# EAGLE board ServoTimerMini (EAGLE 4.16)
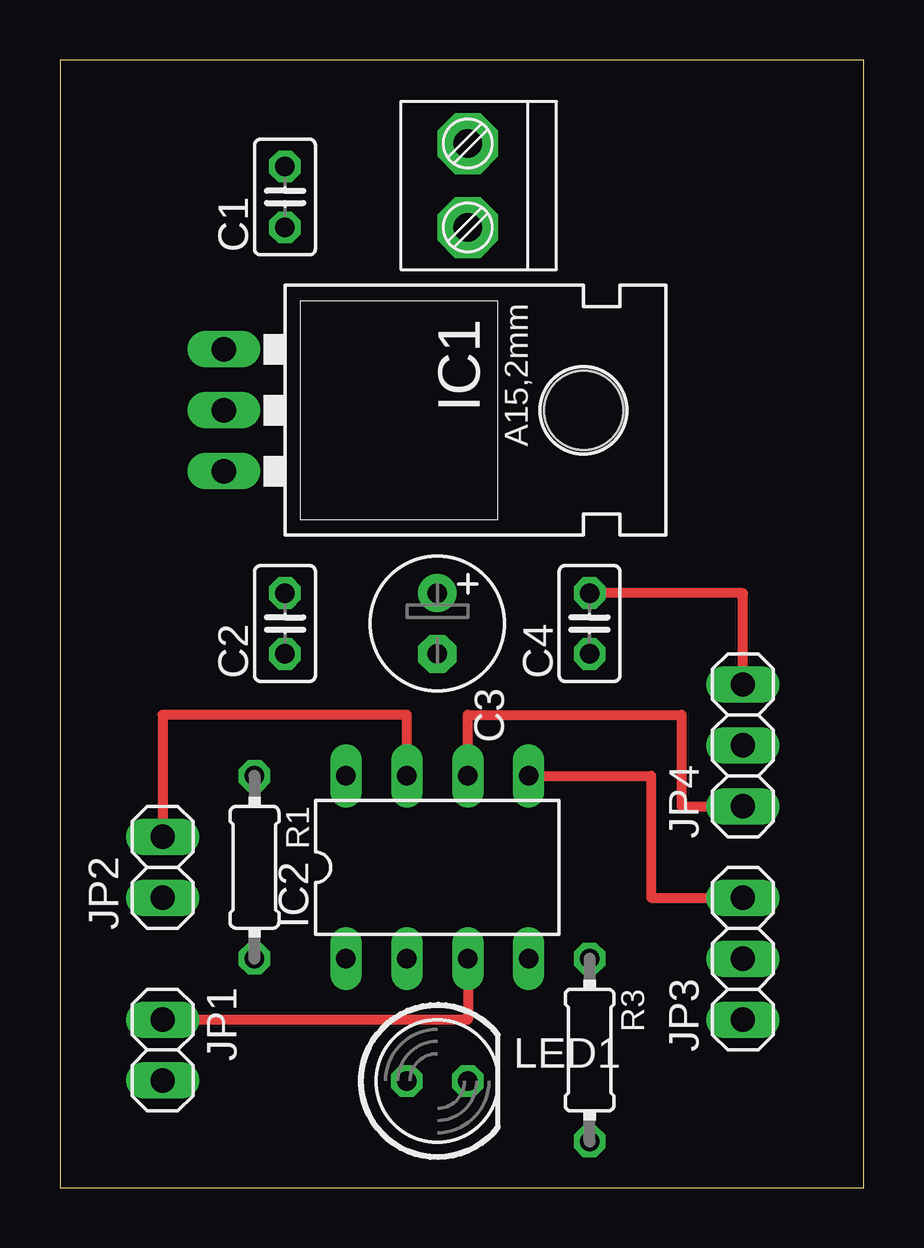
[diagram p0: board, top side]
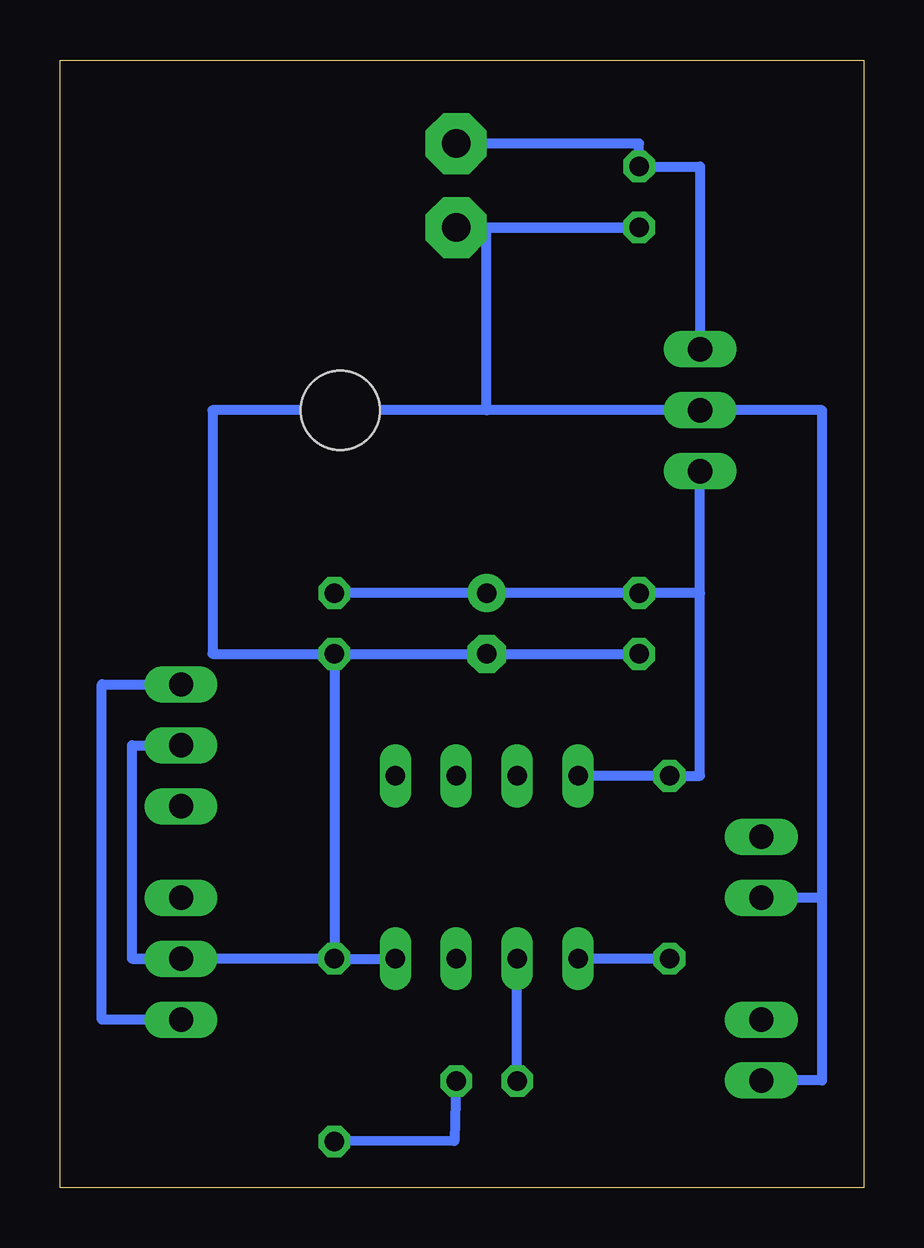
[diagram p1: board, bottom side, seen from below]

Size 33.52 x 47 mm. Coordinates in mm from the lower left corner, seen from the top.
Outline: 0,0 33.52,0 33.52,47 0,47 0,0
Copper layers (1*16): Top 0.035mm / dielectric 1.5mm / Bottom 0.035mm
Design rules "default": minimum track width 10mil, minimum drill 24mil, track to track 8mil, track to pad 8mil, pad to pad 8mil, via to via 8mil, smd to smd 8mil, copper to edge 40mil, drill to drill 8mil, minimum pad ring 10mil, minimum via ring 8mil, stop-mask expansion 4mil, vias tented up to drill 0mil, thermal gap 10mil
Net classes: 0 default: width 0.356 mm, drill 0.254 mm, clearance 0.61 mm; 1 GND: width 0.991 mm, drill 0.254 mm, clearance 0.61 mm; 2 VCC: width 0.356 mm, drill 0.254 mm, clearance 0.61 mm; 3 breit2: width 2.032 mm, drill 0.483 mm, clearance 0.61 mm; 4 breit3: width 2.54 mm, drill 0.61 mm, clearance 0.61 mm

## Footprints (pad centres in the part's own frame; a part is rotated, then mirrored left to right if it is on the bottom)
C025-025X050 = drill 0.813 octagon: 1 -1.27,0; 2 1.27,0
E2,5-6 = drill 0.813 pad 1.6 round: + -1.27,0 | drill 0.813 pad 1.6 octagon: - 1.27,0
78XXL = drill 1.016 long: GND 0,-3.81; IN -2.54,-3.81; OUT 2.54,-3.81 | hole 3.302: 0,11.176
DIL08 = drill 0.813 long: 1 -3.81,-3.81; 2 -1.27,-3.81; 3 1.27,-3.81; 4 3.81,-3.81; 5 3.81,3.81; 6 1.27,3.81; 7 -1.27,3.81; 8 -3.81,3.81
1X02 = drill 1.016 long: 1 -1.27,0; 2 1.27,0
1X03 = drill 1.016 long: 1 -2.54,0; 2 0,0; 3 2.54,0
LED5MM = drill 0.813 octagon: A -1.27,0; K 1.27,0
0204/7 = drill 0.813 octagon: 1 -3.81,0; 2 3.81,0
AKL-2_3,5 = drill 1.2 pad 2.54 octagon: P$1 0,0; P$2 3.5,0

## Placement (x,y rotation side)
C1  100n  [C025-025X050]  9.38,41.29 90 top
C2  100n  [C025-025X050]  9.38,23.51 90 top
C3  100µ  [E2,5-6]  15.73,23.51 270 top
C4  100n  [C025-025X050]  22.08,23.51 90 top
IC1  [78XXL]  10.65,32.4 270 top
IC2  ATTINY45-20P  [DIL08]  15.73,13.35 0 top
JP1  [1X02]  4.28,5.73 270 top
JP2  [1X02]  4.28,13.35 90 top
JP3  [1X03]  28.47,9.54 90 top
JP4  [1X03]  28.47,18.43 90 top
LED1  [LED5MM]  15.73,4.44 0 top
R1  10k  [0204/7]  8.11,13.35 270 top
R3  1K  [0204/7]  22.08,5.73 270 top
X1  [AKL-2_3,5]  17,40.02 90 top

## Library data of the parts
C1-C4 R1 R3 = rcl
IC1 = v-reg
IC2 = avr
JP1-JP4 = pinhead
LED1 = led
X1 = 0mylib

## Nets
+9V: C1.2 IC1.IN X1.P$2
GND: C1.1 C2.1 C3.- C4.1 IC1.GND IC2.4 JP1.2 JP2.1 JP3.2 JP4.2 R3.1 X1.P$1
LED: IC2.2 LED1.A
N$4: LED1.K R3.2
RST: IC2.1 R1.2
SERVO1: IC2.5 JP3.3
SERVO2: IC2.6 JP4.1
TASTER: IC2.3 JP1.1
TRIGGER: IC2.7 JP2.2
VCC: C2.2 C3.+ C4.2 IC1.OUT IC2.8 JP3.1 JP4.3 R1.1

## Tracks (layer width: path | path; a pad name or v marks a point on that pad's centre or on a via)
+9V
  Bottom 0.406: X1.P$2 9.38,43.52 C1.2 6.84,42.56 IC1.IN
GND
  Bottom 0.406: X1.P$1 C1.1 15.73,40.02 15.73,32.4 IC1.GND | R3.1 IC2.4 | C4.1 C3.- C2.1 | C4.1 R3.1 | IC1.GND 27.16,32.4 27.16,22.24 C4.1 | 30.51,9.54 JP3.2 | JP1.2 1.74,4.46 1.74,12.08 | 1.74,12.08 JP2.1 | 1.74,12.08 1.74,32.4 IC1.GND | JP4.2 30.51,18.43 30.51,9.54 | R3.1 30.51,9.54
LED
  Bottom 0.406: LED1.A IC2.2
N$4
  Bottom 0.406: LED1.K 17.08,1.94 R3.2
RST
  Bottom 0.406: R1.2 IC2.1
SERVO1
  Top 0.406: IC2.5 24.64,17.16 24.64,12.08 JP3.3
SERVO2
  Top 0.406: IC2.6 17,19.7 25.91,19.7 25.91,15.89 JP4.1
TASTER
  Top 0.406: IC2.3 17,7 JP1.1
TRIGGER
  Top 0.406: IC2.7 14.46,19.7 4.28,19.7 JP2.2
VCC
  Top 0.406: JP4.3 28.47,24.78 C4.2
  Bottom 0.406: IC2.8 R1.1 6.84,17.16 6.84,24.78 | C4.2 C3.+ C2.2 6.84,24.78 | 6.84,24.78 IC1.OUT | JP3.1 31.78,7 31.78,20.97 JP4.3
